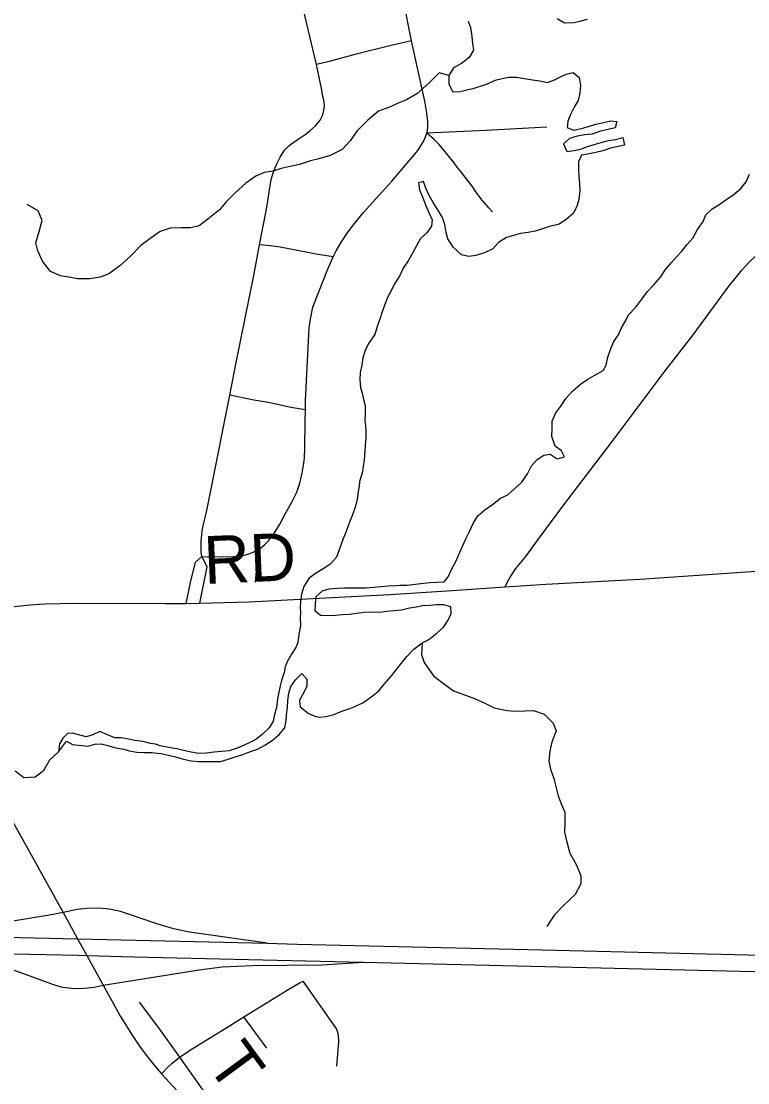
# Model space of a CAD drawing. Extents: x 0 to 36.5, y 0 to 25.3.
# Drawn here: x 4.333 to 5.198, y 17.796 to 19.059 of the extents above; entities that cross this region are included whole.
import ezdxf

# ---------------------------------------------------------------- set-up
doc = ezdxf.new("R2010")
doc.units = 0
for name, color, linetype in [('GM_X_County_Road', 7, 'Continuous'), ('GM_X_County_Road_Text', 7, 'Continuous'), ('GM_X_Interchange_Ramps', 7, 'Continuous'), ('GM_X_Interstate_Route', 7, 'Continuous'), ('GM_X_Major_Lake', 7, 'Continuous'), ('GM_X_Major_River', 7, 'Continuous'), ('GM_X_Minor_River', 7, 'Continuous'), ('GM_X_State_Route', 7, 'Continuous'), ('GM_X_Township_Road', 7, 'Continuous'), ('GM_X_Township_Road_Text', 7, 'Continuous'), ('SH_Data', 7, 'Continuous')]:
    doc.layers.add(name, color=color, linetype=linetype)

msp = doc.modelspace()

# ---------------------------------------------------------------- linework, layer by layer
at = {"layer": 'GM_X_County_Road'}
for points in [[(4.9088, 18.386), (4.9575, 18.3892), (5.0691, 18.3951), (5.3231, 18.4126), (5.3664, 18.4153), (5.3788, 18.4157), (5.3912, 18.4154), (5.4017, 18.4145), (5.4097, 18.4132), (5.4218, 18.4102), (5.4335, 18.4062), (5.4449, 18.4012), (5.456, 18.3957), (5.4947, 18.376), (5.8088, 18.2132), (5.8201, 18.2079), (5.8273, 18.2049)], [(4.5292, 18.3661), (4.5456, 18.3664), (4.6042, 18.3683), (4.7716, 18.3769), (4.846, 18.3816), (4.9088, 18.386)], [(4.2304, 18.3506), (4.2512, 18.3527), (4.325, 18.3627), (4.3435, 18.3645), (4.361, 18.3657), (4.3987, 18.3665), (4.5049, 18.366), (4.5292, 18.3661)]]:
    msp.add_lwpolyline(points, dxfattribs=at)
at = {"layer": 'GM_X_Interchange_Ramps'}
for points in [[(4.3828, 17.9982), (4.3642, 17.9947), (4.3229, 17.988), (4.304, 17.9851), (4.2861, 17.9828), (4.2555, 17.98), (4.2372, 17.9789), (4.1622, 17.9727)], [(4.6257, 17.9616), (4.5332, 17.9747), (4.5272, 17.9759), (4.5144, 17.9789), (4.5036, 17.9819), (4.4919, 17.9857), (4.4606, 17.9965), (4.4511, 17.9994), (4.44, 18.002), (4.4343, 18.0027), (4.4239, 18.0035), (4.4112, 18.0032), (4.3997, 18.0018), (4.3828, 17.9982)], [(4.1784, 17.9527), (4.2756, 17.9413), (4.2935, 17.938), (4.3053, 17.9352), (4.3228, 17.93), (4.3344, 17.9261), (4.3688, 17.9132), (4.3801, 17.9099), (4.3857, 17.9089), (4.397, 17.9077), (4.4083, 17.9081), (4.4197, 17.9096), (4.4305, 17.9119)], [(4.4305, 17.9119), (4.5447, 17.9301), (4.5722, 17.9337), (4.6077, 17.9352), (4.6913, 17.9359), (4.7401, 17.9392)]]:
    msp.add_lwpolyline(points, dxfattribs=at)
at = {"layer": 'GM_X_Interstate_Route'}
for points in [[(2.5228, 17.8746), (2.8824, 17.9016), (3.1111, 17.9191), (3.1262, 17.9203), (3.2312, 17.9287), (3.2621, 17.9308), (3.5708, 17.9546), (3.6, 17.9571), (3.7684, 17.9697), (3.8117, 17.9725), (3.8426, 17.974), (3.8859, 17.9757), (3.9231, 17.9763), (3.9912, 17.9767), (4.1622, 17.9727), (4.4, 17.967), (4.6257, 17.9616)], [(4.6257, 17.9616), (4.6613, 17.9606), (4.953, 17.9539), (5.623, 17.9377), (5.6789, 17.9366), (5.8425, 17.9325), (6.2743, 17.9219), (6.7481, 17.9108)], [(2.5168, 17.8519), (2.9739, 17.889), (3.1256, 17.9005), (3.1938, 17.9057), (3.7403, 17.9483), (3.7961, 17.9523), (3.8458, 17.9546), (3.883, 17.956), (3.9327, 17.957), (3.97, 17.9572), (4.001, 17.957), (4.0678, 17.9551), (4.1784, 17.9527), (4.324, 17.949), (4.3999, 17.9475)], [(4.3999, 17.9475), (4.4109, 17.9473), (4.4668, 17.9456), (4.7401, 17.9392)], [(4.7401, 17.9392), (5.7213, 17.9157), (5.8426, 17.9125), (5.9138, 17.9107), (6.7466, 17.8909), (7.1025, 17.8824)]]:
    msp.add_lwpolyline(points, dxfattribs=at)
at = {"layer": 'GM_X_Major_Lake'}
for points in [[(4.8649, 19.0595), (4.8676, 19.0519), (4.8694, 19.0413)], [(5.0066, 19.0614), (4.9975, 19.0591), (4.991, 19.0576), (4.9796, 19.0573), (4.9709, 19.0623)], [(4.8694, 19.0413), (4.8702, 19.0329), (4.8713, 19.0249), (4.8663, 19.0162), (4.8568, 19.009), (4.8473, 19.0041), (4.842, 18.995), (4.8419, 18.9843), (4.8468, 18.9752), (4.8556, 18.9759), (4.8651, 18.9782), (4.8708, 18.9793), (4.8879, 18.985), (4.897, 18.9891), (4.9054, 18.9914), (4.9134, 18.9929), (4.9225, 18.9929), (4.9414, 18.9898), (4.9502, 18.9886), (4.9593, 18.9863), (4.9677, 18.9897), (4.9756, 18.9935), (4.9814, 18.9965), (4.9901, 18.9984), (4.9969, 18.9923), (4.9988, 18.9828), (4.998, 18.9737), (4.9957, 18.9649), (4.9911, 18.957), (4.9869, 18.9482), (4.9835, 18.9406), (4.9827, 18.933), (4.9903, 18.9296), (4.9998, 18.9319), (5.0081, 18.9341), (5.0169, 18.9367), (5.0264, 18.939), (5.0344, 18.9409), (5.042, 18.9401), (5.04, 18.9325), (5.0317, 18.9306), (5.0226, 18.9284), (5.0127, 18.925), (5.0039, 18.9242), (4.9948, 18.9224), (4.9857, 18.9197), (4.9785, 18.9133), (4.9822, 18.9045), (4.991, 18.9057), (5.0001, 18.9075), (5.0058, 18.9098), (5.0149, 18.9128), (5.0233, 18.9151), (5.032, 18.9173), (5.0408, 18.9188), (5.0491, 18.9211), (5.051, 18.912), (5.0343, 18.9082), (5.0251, 18.9052), (5.0168, 18.9033), (5.0088, 18.9014), (4.9997, 18.8999), (4.9962, 18.892), (4.9962, 18.8832), (4.9966, 18.8745), (4.9973, 18.8661), (4.9977, 18.8578), (4.9965, 18.8471), (4.9942, 18.8388), (4.99, 18.8304), (4.9816, 18.8232), (4.9725, 18.8176), (4.963, 18.8153), (4.9535, 18.8123), (4.9447, 18.8093), (4.9364, 18.8078), (4.9272, 18.8067), (4.9189, 18.8044), (4.9105, 18.8018), (4.901, 18.7961), (4.8941, 18.7885), (4.8843, 18.7836), (4.874, 18.7806), (4.8656, 18.7795), (4.8569, 18.7814), (4.8471, 18.7905), (4.8406, 18.8004), (4.8388, 18.808), (4.8373, 18.8175), (4.8342, 18.8259), (4.829, 18.835), (4.8233, 18.8438), (4.8187, 18.8518), (4.8146, 18.8605), (4.8116, 18.8685), (4.8059, 18.867), (4.807, 18.8587), (4.8104, 18.8503), (4.8142, 18.8408), (4.8179, 18.8324), (4.8221, 18.8229)], [(4.8197, 18.3912), (4.8276, 18.3915), (4.8364, 18.3919), (4.8413, 18.398), (4.8452, 18.4067), (4.8501, 18.4162), (4.8585, 18.4352), (4.8627, 18.4439), (4.8666, 18.4519), (4.8712, 18.4621), (4.8765, 18.4705), (4.8849, 18.4777), (4.894, 18.4841), (4.9035, 18.4917), (4.9123, 18.4955), (4.921, 18.5034), (4.9283, 18.5102), (4.9355, 18.5205), (4.9405, 18.53), (4.947, 18.5375), (4.955, 18.5428), (4.9626, 18.544), (4.9709, 18.5386), (4.9796, 18.5409), (4.9759, 18.5481), (4.9683, 18.5535), (4.9645, 18.5649), (4.9649, 18.574), (4.965, 18.5831), (4.9692, 18.593), (4.9753, 18.6013), (4.981, 18.6104), (4.989, 18.6188), (4.9985, 18.6275), (5.0073, 18.6332), (5.0156, 18.6381), (5.0255, 18.6437), (5.0293, 18.6498), (5.0313, 18.6593), (5.0347, 18.6699), (5.0385, 18.6783), (5.0439, 18.6859), (5.0473, 18.6942), (5.053, 18.7041), (5.0557, 18.7098), (5.0645, 18.7189), (5.0717, 18.7287), (5.0782, 18.7375), (5.0858, 18.7454), (5.0938, 18.7549), (5.0999, 18.764), (5.1068, 18.772), (5.1137, 18.7796), (5.119, 18.7852), (5.1251, 18.7932), (5.1323, 18.8012), (5.1377, 18.8114), (5.1446, 18.8209), (5.148, 18.8289), (5.1552, 18.8361), (5.1632, 18.841), (5.1716, 18.8467), (5.1815, 18.8535), (5.1895, 18.8603), (5.196, 18.8682), (5.1998, 18.8774)], [(4.8221, 18.8229), (4.8213, 18.8153), (4.8156, 18.8073), (4.808, 18.8009), (4.8038, 18.7929), (4.7988, 18.7834), (4.7935, 18.7743), (4.7877, 18.7656), (4.7831, 18.7561), (4.7778, 18.7474), (4.7736, 18.7394), (4.769, 18.7307), (4.7656, 18.7223), (4.7625, 18.7136), (4.7598, 18.7049), (4.7571, 18.6973), (4.7537, 18.6863), (4.7461, 18.6757), (4.7422, 18.6673), (4.7396, 18.6586), (4.7384, 18.6498), (4.7365, 18.6411), (4.7361, 18.6324), (4.7368, 18.6232), (4.7387, 18.6168), (4.7409, 18.6076), (4.7424, 18.6019), (4.7424, 18.5932), (4.742, 18.5841), (4.7427, 18.5776), (4.7431, 18.5708), (4.7431, 18.5628), (4.7423, 18.5544), (4.7419, 18.548), (4.7411, 18.5373), (4.7388, 18.5214), (4.7357, 18.5115), (4.7353, 18.5054), (4.7338, 18.4994), (4.733, 18.4906), (4.7307, 18.4819), (4.7272, 18.4716), (4.723, 18.461), (4.7196, 18.4519), (4.7157, 18.4424), (4.7115, 18.4299), (4.7081, 18.4215), (4.7008, 18.4132), (4.6932, 18.4079), (4.6833, 18.4018), (4.6753, 18.3958), (4.6692, 18.3866), (4.6666, 18.3772), (4.6654, 18.3688), (4.665, 18.3612), (4.6653, 18.3555), (4.665, 18.3498), (4.6653, 18.3395), (4.6634, 18.3296), (4.6622, 18.3198), (4.6599, 18.3137), (4.6546, 18.3057), (4.6496, 18.2966), (4.6473, 18.2909), (4.6458, 18.2841), (4.6427, 18.2746), (4.6412, 18.2681), (4.64, 18.2624), (4.6381, 18.2526), (4.6369, 18.2423), (4.6346, 18.2339), (4.6327, 18.226), (4.6281, 18.218), (4.6197, 18.2104), (4.6121, 18.2043), (4.6041, 18.2002), (4.5984, 18.1975), (4.59, 18.1938), (4.5805, 18.1907), (4.5714, 18.19), (4.5627, 18.1893), (4.5536, 18.1882), (4.5444, 18.1878), (4.5353, 18.1893), (4.5262, 18.1913), (4.5182, 18.1932), (4.5125, 18.194), (4.5042, 18.1955), (4.4985, 18.1967), (4.4928, 18.1986), (4.4867, 18.1997), (4.4776, 18.2017), (4.4681, 18.2032), (4.4605, 18.2048), (4.4518, 18.2063), (4.4442, 18.2063), (4.4355, 18.2098), (4.4264, 18.2136), (4.418, 18.2098), (4.4104, 18.2075), (4.394, 18.212)], [(4.3939, 18.1983), (4.4123, 18.1965), (4.4206, 18.1988), (4.4282, 18.1991), (4.4362, 18.1972), (4.4457, 18.1945), (4.4552, 18.1926), (4.4616, 18.1907), (4.4704, 18.1891), (4.4787, 18.1887), (4.4882, 18.1887), (4.4992, 18.1875), (4.5083, 18.1856), (4.5167, 18.1837), (4.5262, 18.181), (4.5353, 18.1787), (4.5444, 18.1779), (4.5611, 18.1779), (4.5702, 18.1782), (4.5782, 18.1805), (4.5877, 18.1835), (4.5968, 18.1865), (4.6026, 18.1888), (4.6083, 18.1907), (4.6143, 18.1929), (4.6231, 18.1975), (4.6318, 18.2032), (4.6398, 18.2104), (4.6467, 18.2183), (4.6482, 18.2267), (4.6486, 18.2335), (4.6498, 18.2423), (4.6502, 18.2506), (4.6514, 18.2594), (4.6537, 18.2673), (4.6594, 18.2753), (4.667, 18.2829), (4.6727, 18.276), (4.6727, 18.2677), (4.6692, 18.2601), (4.6643, 18.2513), (4.665, 18.243), (4.6745, 18.2357), (4.6824, 18.2319), (4.6881, 18.2308), (4.6957, 18.2315), (4.7049, 18.2341), (4.7144, 18.2379), (4.7239, 18.2413), (4.73, 18.2436), (4.7395, 18.2481), (4.7505, 18.2557), (4.7585, 18.2621), (4.7654, 18.2705), (4.7738, 18.2799), (4.7779, 18.2856), (4.7852, 18.2947), (4.7921, 18.3031), (4.8001, 18.3118), (4.81, 18.3194), (4.8183, 18.3235), (4.8275, 18.3307), (4.8355, 18.3379), (4.8412, 18.3463), (4.8446, 18.3542), (4.8443, 18.3622), (4.8359, 18.3645), (4.8276, 18.3646), (4.8188, 18.3638), (4.8105, 18.3635), (4.8029, 18.362), (4.7949, 18.3605), (4.7854, 18.3582), (4.7766, 18.3575), (4.7683, 18.3567), (4.7588, 18.3556), (4.7493, 18.356), (4.7413, 18.3553), (4.7326, 18.3542), (4.7235, 18.3531), (4.7155, 18.3527), (4.7071, 18.352), (4.6984, 18.3516), (4.6893, 18.352), (4.6828, 18.357), (4.6832, 18.3657), (4.684, 18.3744), (4.6916, 18.3813), (4.6996, 18.3835), (4.7095, 18.3843), (4.7179, 18.385), (4.7433, 18.3849), (4.7528, 18.3857), (4.7608, 18.3864), (4.7699, 18.3871), (4.7783, 18.3875), (4.784, 18.3879), (4.7919, 18.3882), (4.8022, 18.3893), (4.8117, 18.3904), (4.8197, 18.3912)], [(4.394, 18.212), (4.3879, 18.2113), (4.3825, 18.206), (4.3785, 18.1993), (4.3772, 18.1897)], [(4.3772, 18.1897), (4.3868, 18.2021), (4.3939, 18.1983)]]:
    msp.add_lwpolyline(points, dxfattribs=at)
at = {"layer": 'GM_X_Major_River'}
msp.add_lwpolyline([(4.3772, 18.1897), (4.3665, 18.1795), (4.3592, 18.1667), (4.3496, 18.1595), (4.3359, 18.1585), (4.3258, 18.1666)], dxfattribs=at)
at = {"layer": 'GM_X_Minor_River'}
for points in [[(4.842, 18.995), (4.8306, 18.998), (4.8184, 18.9859), (4.8039, 18.973), (4.7917, 18.9658), (4.7815, 18.9617), (4.7712, 18.9572), (4.7583, 18.9523), (4.7457, 18.9417), (4.7327, 18.9291), (4.7244, 18.917), (4.7148, 18.9068), (4.7008, 18.8996), (4.6871, 18.8955), (4.6772, 18.8932), (4.6643, 18.8887), (4.6529, 18.8864), (4.6422, 18.8842), (4.6327, 18.8808), (4.6221, 18.8793), (4.6122, 18.8751), (4.6004, 18.8668), (4.5874, 18.8551), (4.5768, 18.8444), (4.5688, 18.835), (4.5551, 18.8236), (4.5448, 18.816), (4.5349, 18.8134), (4.5231, 18.8134), (4.5102, 18.8131), (4.4984, 18.8089), (4.4878, 18.8014), (4.4752, 18.7923), (4.463, 18.7798), (4.4504, 18.7684), (4.4371, 18.7586), (4.4269, 18.7548), (4.4147, 18.7529), (4.3998, 18.7529)], [(4.3998, 18.7529), (4.3917, 18.7543), (4.3796, 18.7563), (4.3679, 18.7613), (4.3581, 18.7739), (4.3526, 18.7861), (4.3504, 18.7956), (4.3543, 18.8089), (4.3578, 18.8222), (4.353, 18.8336), (4.3402, 18.8413)], [(4.81, 18.3194), (4.8095, 18.3053), (4.8125, 18.2958), (4.8235, 18.2802), (4.8341, 18.2722), (4.8474, 18.2623), (4.8573, 18.2588), (4.8724, 18.2531), (4.8849, 18.2477), (4.8959, 18.242), (4.9088, 18.2393), (4.9187, 18.2381), (4.9324, 18.2385), (4.9427, 18.2388), (4.9552, 18.2346), (4.9662, 18.2239), (4.9695, 18.2144), (4.9646, 18.2011), (4.9623, 18.1905), (4.9611, 18.1787), (4.9629, 18.1688), (4.9667, 18.1578), (4.9697, 18.1467), (4.972, 18.1372), (4.9757, 18.1277), (4.9799, 18.1178), (4.9798, 18.1053), (4.9794, 18.0939), (4.9821, 18.0836), (4.9858, 18.0688), (4.9937, 18.0547), (4.999, 18.0421), (4.999, 18.0326), (4.9921, 18.0197), (4.9788, 18.0072), (4.9674, 17.9951), (4.9586, 17.9818)]]:
    msp.add_lwpolyline(points, dxfattribs=at)
at = {"layer": 'GM_X_State_Route'}
msp.add_line((4.3828, 17.9982), (4.3972, 17.9722), dxfattribs=at)
for points in [[(4.3187, 18.1138), (4.3248, 18.1026), (4.3828, 17.9982)], [(4.3972, 17.9722), (4.4, 17.967), (4.4109, 17.9473), (4.4305, 17.9119), (4.4513, 17.8746), (4.4642, 17.8533), (4.4746, 17.8379), (4.482, 17.8279), (4.4907, 17.8168), (4.4998, 17.8062)], [(4.4998, 17.8062), (4.5187, 17.7859), (4.5321, 17.7729), (4.5503, 17.7566), (4.5838, 17.7283), (4.5974, 17.7156), (4.6104, 17.7023), (4.6253, 17.6855), (4.6484, 17.6579)]]:
    msp.add_lwpolyline(points, dxfattribs=at)
at = {"layer": 'GM_X_Township_Road'}
msp.add_line((4.6252, 17.8368), (4.5981, 17.874), dxfattribs=at)
for points in [[(4.6843, 19.0081), (4.6631, 19.0983), (4.65, 19.1525), (4.6307, 19.2464)], [(4.7975, 19.0359), (4.793, 19.0581), (4.7857, 19.0976), (4.7841, 19.1099), (4.784, 19.1166), (4.7847, 19.1223), (4.7862, 19.1283), (4.7888, 19.134), (4.7921, 19.1392), (4.7962, 19.1439), (4.8005, 19.1482), (4.8052, 19.1523), (4.8121, 19.1576)], [(4.7975, 19.0359), (4.7733, 19.0305), (4.7317, 19.0202), (4.6995, 19.0115), (4.6843, 19.0081)], [(4.8158, 18.9261), (4.8167, 18.9293), (4.8171, 18.9338), (4.8171, 18.9399), (4.8154, 18.9522), (4.8132, 18.9644), (4.7975, 19.0359)], [(4.6167, 18.7933), (4.6249, 18.8356), (4.6305, 18.8709), (4.6331, 18.8802), (4.637, 18.8898), (4.6412, 18.8977), (4.6464, 18.9058), (4.6508, 18.9102), (4.6535, 18.9125), (4.6613, 18.9184), (4.6709, 18.9247), (4.6765, 18.929), (4.6833, 18.935), (4.6889, 18.9416), (4.6916, 18.9471), (4.6925, 18.9498), (4.6933, 18.9531), (4.694, 18.9589), (4.6932, 18.9654), (4.6916, 18.9714), (4.6909, 18.9775), (4.6843, 19.0081)], [(4.9584, 18.9334), (4.8865, 18.9292), (4.8158, 18.9261)], [(4.7042, 18.7788), (4.7079, 18.7861), (4.7142, 18.7967), (4.7211, 18.807), (4.7284, 18.817), (4.74, 18.8314), (4.7741, 18.8691), (4.8011, 18.9007), (4.8049, 18.9057), (4.8116, 18.9162), (4.8143, 18.9218), (4.8158, 18.9261)], [(4.8938, 18.8326), (4.8894, 18.8371), (4.8815, 18.8465), (4.8741, 18.8563), (4.8707, 18.8614), (4.8557, 18.8808), (4.8517, 18.8855), (4.8484, 18.8907), (4.8306, 18.9126), (4.8247, 18.9184), (4.8158, 18.9261)], [(4.5813, 18.6144), (4.5888, 18.6531), (4.6098, 18.7565), (4.6167, 18.7933)], [(4.7042, 18.7788), (4.6862, 18.7816), (4.6412, 18.7903), (4.6291, 18.792), (4.6167, 18.7933)], [(4.6712, 18.5967), (4.6714, 18.608), (4.6758, 18.6945), (4.6773, 18.7048), (4.6802, 18.7188), (4.682, 18.7241), (4.6974, 18.7636), (4.7042, 18.7788)], [(4.9088, 18.386), (4.9117, 18.3921), (4.9148, 18.3975), (4.9218, 18.4077), (4.9336, 18.4221), (4.9481, 18.4422), (4.9777, 18.482), (5.034, 18.556), (5.0983, 18.6416), (5.1327, 18.6859), (5.1756, 18.7442), (5.191, 18.7636), (5.1993, 18.7727), (5.2064, 18.7794)], [(4.5481, 18.4223), (4.5473, 18.4279), (4.547, 18.434), (4.547, 18.4402), (4.5484, 18.4526), (4.5495, 18.4587), (4.5537, 18.4768), (4.559, 18.5028), (4.5813, 18.6144)], [(4.6712, 18.5967), (4.6539, 18.5997), (4.6271, 18.6053), (4.6099, 18.6082), (4.5813, 18.6144)], [(4.612, 18.4289), (4.6182, 18.4326), (4.623, 18.4365), (4.6273, 18.4408), (4.6345, 18.4503), (4.6408, 18.4605), (4.6464, 18.4712), (4.6552, 18.487), (4.6605, 18.498), (4.6626, 18.5036), (4.6645, 18.5093), (4.6675, 18.5213), (4.6693, 18.5333), (4.67, 18.5394), (4.6707, 18.5517), (4.6708, 18.5827), (4.6712, 18.5967)], [(4.5481, 18.4223), (4.5795, 18.4217), (4.5912, 18.4225), (4.597, 18.4235), (4.6026, 18.425), (4.6081, 18.427), (4.612, 18.4289)], [(4.6119, 18.3914), (4.6139, 18.4137), (4.6141, 18.4186), (4.613, 18.4246), (4.612, 18.4289)], [(4.5292, 18.3661), (4.5346, 18.391), (4.5403, 18.4155), (4.5481, 18.4223)], [(4.5456, 18.3664), (4.5542, 18.4098), (4.5481, 18.4223)], [(4.5981, 17.874), (4.6494, 17.9057), (4.665, 17.915), (4.6684, 17.9166)], [(4.7087, 17.8155), (4.7108, 17.8448), (4.7105, 17.8522), (4.7085, 17.8594), (4.6684, 17.9166)], [(4.4734, 17.8916), (4.4964, 17.8609), (4.5214, 17.826)], [(4.5214, 17.826), (4.5363, 17.8361), (4.5776, 17.8612), (4.5981, 17.874)], [(4.4998, 17.8062), (4.5075, 17.8143), (4.5127, 17.8191), (4.5214, 17.826)], [(4.5214, 17.826), (4.5558, 17.7774), (4.5631, 17.7678), (4.5707, 17.7584), (4.6253, 17.6855)]]:
    msp.add_lwpolyline(points, dxfattribs=at)
at = {"layer": 'SH_Data'}
for points in [[(4.3187, 18.1138), (4.3248, 18.1026), (4.3828, 17.9982)], [(4.3972, 17.9722), (4.4, 17.967), (4.4109, 17.9473), (4.4305, 17.9119), (4.4513, 17.8746), (4.4642, 17.8533), (4.4746, 17.8379), (4.482, 17.8279), (4.4907, 17.8168), (4.4998, 17.8062)], [(4.4998, 17.8062), (4.5187, 17.7859), (4.5321, 17.7729), (4.5503, 17.7566), (4.5838, 17.7283), (4.5974, 17.7156), (4.6104, 17.7023), (4.6253, 17.6855), (4.6484, 17.6579)]]:
    msp.add_lwpolyline(points, dxfattribs=at)

# ---------------------------------------------------------------- texts
at = {"layer": 'GM_X_County_Road_Text'}
msp.add_text('RD', height=0.05682, rotation=2.4455, dxfattribs=at).set_placement((4.5513, 18.3894))
at = {"layer": 'GM_X_Township_Road_Text'}
msp.add_text('T', height=0.0568, rotation=306.3262, dxfattribs=at).set_placement((4.5523, 17.8175))

doc.saveas('drawing.dxf')
